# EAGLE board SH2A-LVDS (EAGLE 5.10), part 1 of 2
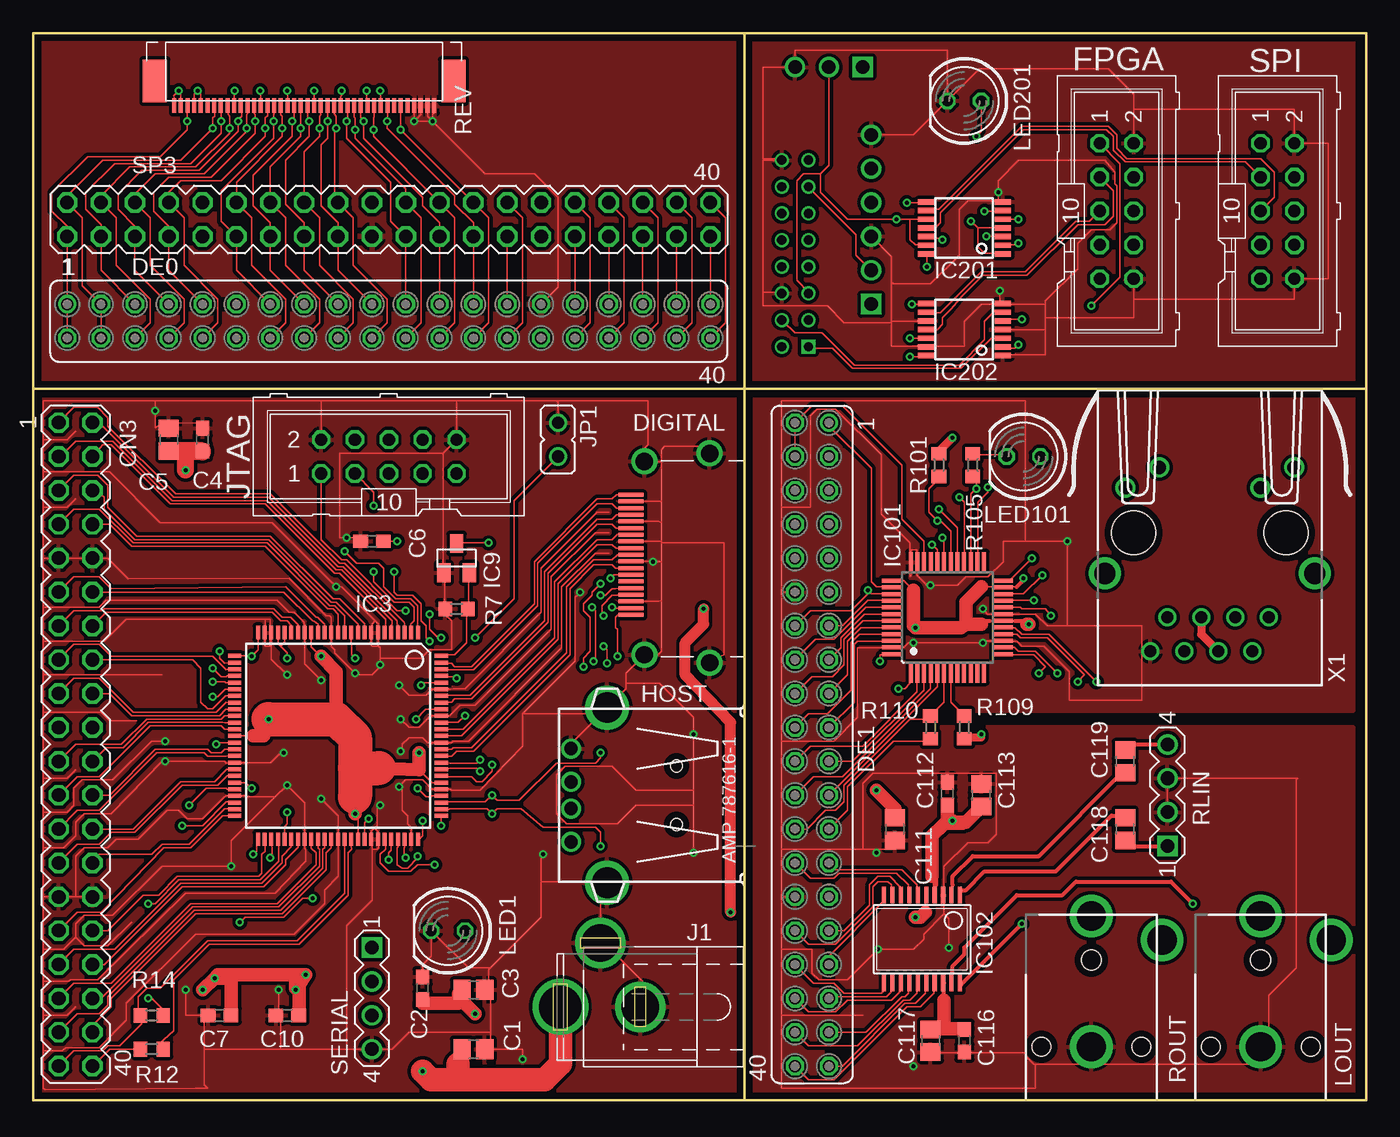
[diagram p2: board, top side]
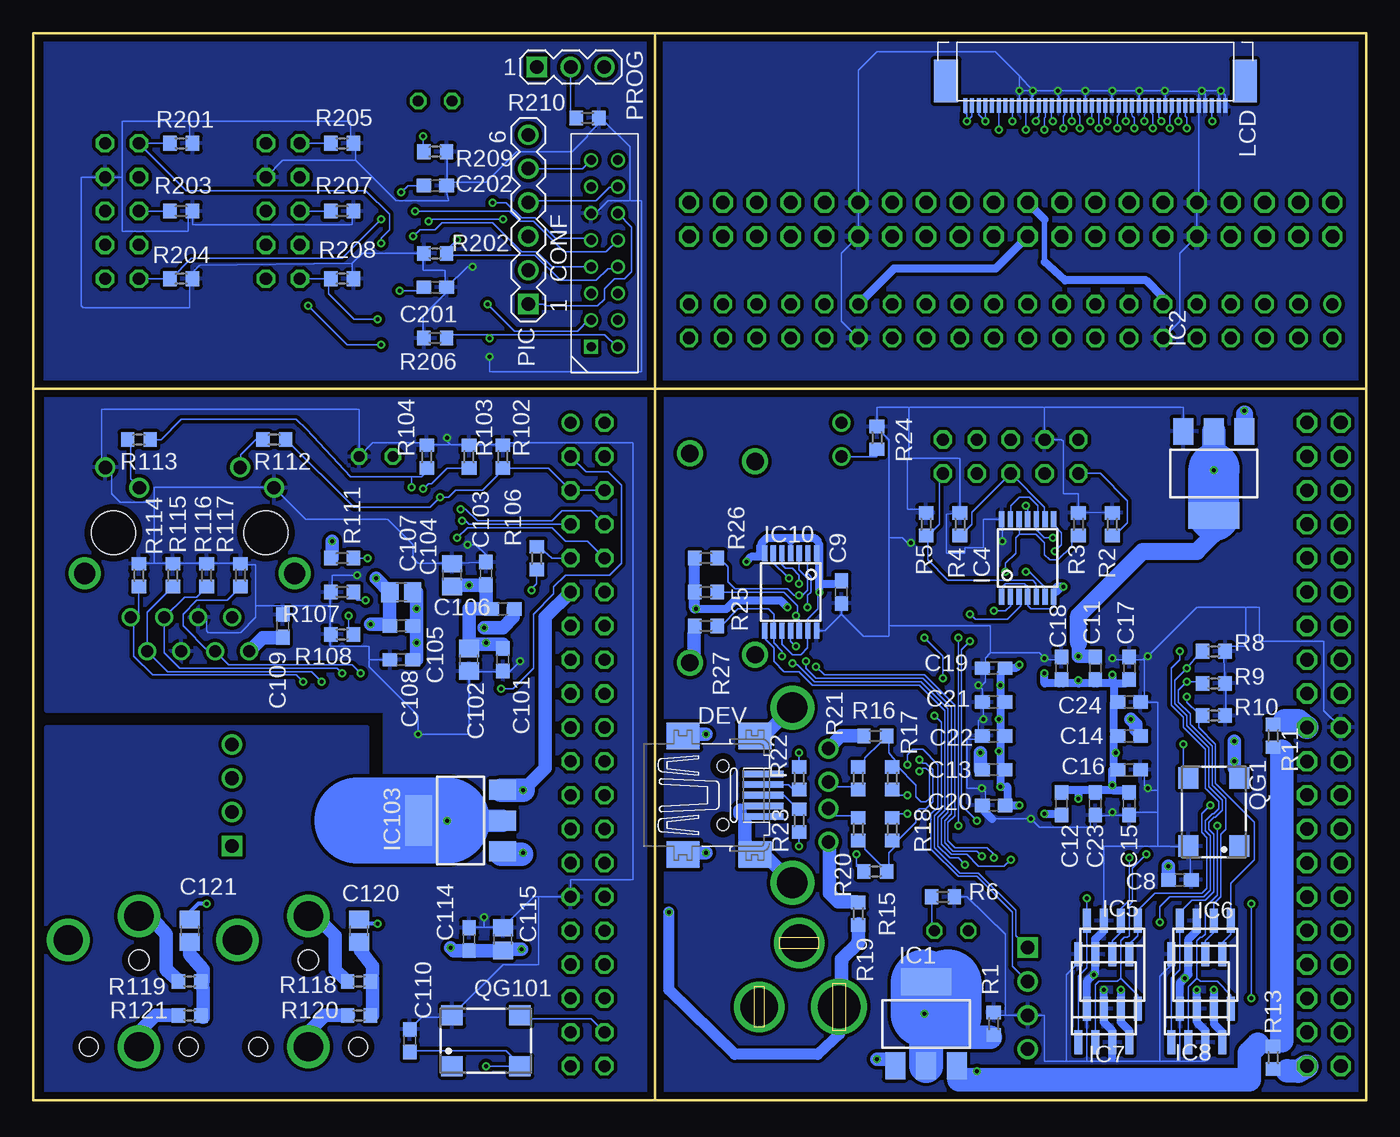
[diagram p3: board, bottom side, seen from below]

Size 100 x 80 mm. Coordinates in mm from the lower left corner, seen from the top.
Outline: 53.34,0 0,0 0,53.34
Outline: 53.34,0 100,0 100,53.34
Outline: 100,53.34 100,80 53.34,80
Outline: 53.34,80 0,80 0,53.34
Outline: 53.34,53.34 53.34,0
Outline: 0,53.34 53.34,53.34
Outline: 53.34,53.34 53.34,80
Outline: 53.34,53.34 100,53.34
Copper layers (1*16): Top 0.035mm / dielectric 1.53mm / Bottom 0.035mm
Design rules "pban_5mil-l2 *": minimum track width 5mil, minimum drill 0.3mm, track to track 5mil, track to pad 0.229mm, pad to pad 5mil, via to via 5mil, smd to smd 5mil, copper to edge 0.5mm, drill to drill 0.5mm, minimum pad ring 0.15mm, minimum via ring 0.15mm, stop-mask expansion 4mil, vias tented up to drill 0.35mm, thermal gap 10mil

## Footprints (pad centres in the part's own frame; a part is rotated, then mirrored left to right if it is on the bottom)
C2012 = smd 1.3 x 1.5: 1 -0.85,0; 2 0.85,0
C1608 = smd 1.1 x 1: 1 -0.85,0; 2 0.85,0
MA20-2 = drill 1.016 octagon: 1 -24.13,-1.27; 2 -24.13,1.27; 3 -21.59,-1.27; 4 -21.59,1.27; 5 -19.05,-1.27; 6 -19.05,1.27; 7 -16.51,-1.27; 8 -16.51,1.27; 9 -13.97,-1.27; 10 -13.97,1.27; 11 -11.43,-1.27; 12 -11.43,1.27; 13 -8.89,-1.27; 14 -8.89,1.27; 15 -6.35,-1.27; 16 -6.35,1.27; 17 -3.81,-1.27; 18 -3.81,1.27; 19 -1.27,-1.27; 20 -1.27,1.27; 21 1.27,-1.27; 22 1.27,1.27; 23 3.81,-1.27; 24 3.81,1.27; 25 6.35,-1.27; 26 6.35,1.27; 27 8.89,-1.27; 28 8.89,1.27; 29 11.43,-1.27; 30 11.43,1.27; 31 13.97,-1.27; 32 13.97,1.27; 33 16.51,-1.27; 34 16.51,1.27; 35 19.05,-1.27; 36 19.05,1.27; 37 21.59,-1.27; 38 21.59,1.27; 39 24.13,-1.27; 40 24.13,1.27
PHDSS-16 = drill 0.7 square: P$1 1,7 | drill 0.7 round: P$2 -1,7; P$3 1,5; P$4 -1,5; P$5 1,3; P$6 -1,3; P$7 1,1; P$8 -1,1; P$9 1,-1; P$10 -1,-1; P$11 1,-3; P$12 -1,-3; P$13 1,-5; P$14 -1,-5; P$15 1,-7; P$16 -1,-7
FE20-2 = drill 0.914 round: 1 -24.13,1.27 | drill 0.914 octagon: 2 -24.13,-1.27; 3 -21.59,1.27; 4 -21.59,-1.27; 5 -19.05,1.27; 6 -19.05,-1.27; 7 -16.51,1.27; 8 -16.51,-1.27; 9 -13.97,1.27; 10 -13.97,-1.27; 11 -11.43,1.27; 12 -11.43,-1.27; 13 -8.89,1.27; 14 -8.89,-1.27; 15 -6.35,1.27; 16 -6.35,-1.27; 17 -3.81,1.27; 18 -3.81,-1.27; 19 -1.27,1.27; 20 -1.27,-1.27; 21 1.27,1.27; 22 1.27,-1.27; 23 3.81,1.27; 24 3.81,-1.27; 25 6.35,1.27; 26 6.35,-1.27; 27 8.89,1.27; 28 8.89,-1.27; 29 11.43,1.27; 30 11.43,-1.27; 31 13.97,1.27; 32 13.97,-1.27; 33 16.51,1.27; 34 16.51,-1.27; 35 19.05,1.27; 36 19.05,-1.27; 37 21.59,1.27; 38 21.59,-1.27; 39 24.13,1.27; 40 24.13,-1.27
32005-201A = smd 3.1 x 0.5: 1 3,1.6; 2 3,0.8; 3 3,0; 4 3,-0.8; 5 3,-1.6 | smd 2.5 x 2: M1 -3,-4.45; M2 -3,4.45; M3 2.4,4.45; M4 2.4,-4.45 | hole 0.9: 0,2.2; 0,-2.2
HDMI-FCI-A-UPDATE = smd 0.3 x 1.9: 1 4.75,8.5; 2 4.25,8.5; 3 3.75,8.5; 4 3.25,8.5; 5 2.75,8.5; 6 2.25,8.5; 7 1.75,8.5; 8 1.25,8.5; 9 0.75,8.5; 10 0.25,8.5; 11 -0.25,8.5; 12 -0.75,8.5; 13 -1.25,8.5; 14 -1.75,8.5; 15 -2.25,8.5; 16 -2.75,8.5; 17 -3.25,8.5; 18 -3.75,8.5; 19 -4.25,8.5 | drill 1.3 round: 20 -7.85,2.6; 21 7.85,2.6; 22 -7.25,7.5; 23 7.25,7.5
ML10 = drill 0.914 octagon: 1 -5.08,-1.27; 2 -5.08,1.27; 3 -2.54,-1.27; 4 -2.54,1.27; 5 0,-1.27; 6 0,1.27; 7 2.54,-1.27; 8 2.54,1.27; 9 5.08,-1.27; 10 5.08,1.27
USB = drill 1 round: 1 -3.5,12.99; 2 -1,12.99; 3 1,12.99; 4 3.5,12.99 | drill 2.3 round: P$1 -6.57,10.28; P$2 6.57,10.28
SOT223 = smd 1.5 x 2: 1 -2.3,-3.15; 2 0,-3.15; 3 2.3,-3.15 | smd 3.8 x 2: 4 0,3.15
VQ100 = smd 1 x 0.3: 1 -7.75,6; 2 -7.75,5.5; 3 -7.75,5; 4 -7.75,4.5; 5 -7.75,4; 6 -7.75,3.5; 7 -7.75,3; 8 -7.75,2.5; 9 -7.75,2; 10 -7.75,1.5; 11 -7.75,1; 12 -7.75,0.5; 13 -7.75,0; 14 -7.75,-0.5; 15 -7.75,-1; 16 -7.75,-1.5; 17 -7.75,-2; 18 -7.75,-2.5; 19 -7.75,-3; 20 -7.75,-3.5; 21 -7.75,-4; 22 -7.75,-4.5; 23 -7.75,-5; 24 -7.75,-5.5; 25 -7.75,-6; 51 7.75,-6; 52 7.75,-5.5; 53 7.75,-5; 54 7.75,-4.5; 55 7.75,-4; 56 7.75,-3.5; 57 7.75,-3; 58 7.75,-2.5; 59 7.75,-2; 60 7.75,-1.5; 61 7.75,-1; 62 7.75,-0.5; 63 7.75,0; 64 7.75,0.5; 65 7.75,1; 66 7.75,1.5; 67 7.75,2; 68 7.75,2.5; 69 7.75,3; 70 7.75,3.5; 71 7.75,4; 72 7.75,4.5; 73 7.75,5; 74 7.75,5.5; 75 7.75,6 | smd 0.3 x 1: 26 -6,-7.75; 27 -5.5,-7.75; 28 -5,-7.75; 29 -4.5,-7.75; 30 -4,-7.75; 31 -3.5,-7.75; 32 -3,-7.75; 33 -2.5,-7.75; 34 -2,-7.75; 35 -1.5,-7.75; 36 -1,-7.75; 37 -0.5,-7.75; 38 0,-7.75; 39 0.5,-7.75; 40 1,-7.75; 41 1.5,-7.75; 42 2,-7.75; 43 2.5,-7.75; 44 3,-7.75; 45 3.5,-7.75; 46 4,-7.75; 47 4.5,-7.75; 48 5,-7.75; 49 5.5,-7.75; 50 6,-7.75; 76 6,7.75; 77 5.5,7.75; 78 5,7.75; 79 4.5,7.75; 80 4,7.75; 81 3.5,7.75; 82 3,7.75; 83 2.5,7.75; 84 2,7.75; 85 1.5,7.75; 86 1,7.75; 87 0.5,7.75; 88 0,7.75; 89 -0.5,7.75; 90 -1,7.75; 91 -1.5,7.75; 92 -2,7.75; 93 -2.5,7.75; 94 -3,7.75; 95 -3.5,7.75; 96 -4,7.75; 97 -4.5,7.75; 98 -5,7.75; 99 -5.5,7.75; 100 -6,7.75
PW_R-PDSO-G14 = smd 0.4 x 1.2: 1 -1.95,-2.9; 2 -1.3,-2.9; 3 -0.65,-2.9; 4 0,-2.9; 5 0.65,-2.9; 6 1.3,-2.9; 7 1.95,-2.9; 8 1.95,2.9; 9 1.3,2.9; 10 0.65,2.9; 11 0,2.9; 12 -0.65,2.9; 13 -1.3,2.9; 14 -1.95,2.9
AT45DB = smd 0.6 x 1.8: 1 -1.905,-3.3; 2 -0.635,-3.3; 3 0.635,-3.3; 4 1.905,-3.3; 5 1.905,3.3; 6 0.635,3.3; 7 -0.635,3.3; 8 -1.905,3.3
SOT23 = smd 1 x 1.4: 1 -0.95,-1.1; 2 0.95,-1.1; 3 0,1.1
LQFP48 = smd 1.5 x 0.3: 1 -4.15,2.75; 2 -4.15,2.25; 3 -4.15,1.75; 4 -4.15,1.25; 5 -4.15,0.75; 6 -4.15,0.25; 7 -4.15,-0.25; 8 -4.15,-0.75; 9 -4.15,-1.25; 10 -4.15,-1.75; 11 -4.15,-2.25; 12 -4.15,-2.75; 25 4.15,-2.75; 26 4.15,-2.25; 27 4.15,-1.75; 28 4.15,-1.25; 29 4.15,-0.75; 30 4.15,-0.25; 31 4.15,0.25; 32 4.15,0.75; 33 4.15,1.25; 34 4.15,1.75; 35 4.15,2.25; 36 4.15,2.75 | smd 0.3 x 1.5: 13 -2.75,-4.15; 14 -2.25,-4.15; 15 -1.75,-4.15; 16 -1.25,-4.15; 17 -0.75,-4.15; 18 -0.25,-4.15; 19 0.25,-4.15; 20 0.75,-4.15; 21 1.25,-4.15; 22 1.75,-4.15; 23 2.25,-4.15; 24 2.75,-4.15; 37 2.75,4.15; 38 2.25,4.15; 39 1.75,4.15; 40 1.25,4.15; 41 0.75,4.15; 42 0.25,4.15; 43 -0.25,4.15; 44 -0.75,4.15; 45 -1.25,4.15; 46 -1.75,4.15; 47 -2.25,4.15; 48 -2.75,4.15
SSOP20 = smd 0.305 x 1.245: 1 -2.857,-3.302; 2 -2.222,-3.302; 3 -1.587,-3.302; 4 -0.952,-3.302; 5 -0.317,-3.302; 6 0.318,-3.302; 7 0.953,-3.302; 8 1.588,-3.302; 9 2.223,-3.302; 10 2.858,-3.302; 11 2.858,3.302; 12 2.223,3.302; 13 1.588,3.302; 14 0.953,3.302; 15 0.318,3.302; 16 -0.317,3.302; 17 -0.952,3.302; 18 -1.587,3.302; 19 -2.222,3.302; 20 -2.857,3.302
SPC4077A = drill 2.8 round: 1 -3,0; 2 0,-4.8 | drill 3.2 round: 3 3,0
JP1A = drill 0.914 round: 1 0,-1.27; 2 0,1.27
FFC-40-0.5B-TYCO = smd 1.1 x 0.3: 1 -0.35,9.75; 2 -0.35,9.25; 3 -0.35,8.75; 4 -0.35,8.25; 5 -0.35,7.75; 6 -0.35,7.25; 7 -0.35,6.75; 8 -0.35,6.25; 9 -0.35,5.75; 10 -0.35,5.25; 11 -0.35,4.75; 12 -0.35,4.25; 13 -0.35,3.75; 14 -0.35,3.25; 15 -0.35,2.75; 16 -0.35,2.25; 17 -0.35,1.75; 18 -0.35,1.25; 19 -0.35,0.75; 20 -0.35,0.25; 21 -0.35,-0.25; 22 -0.35,-0.75; 23 -0.35,-1.25; 24 -0.35,-1.75; 25 -0.35,-2.25; 26 -0.35,-2.75; 27 -0.35,-3.25; 28 -0.35,-3.75; 29 -0.35,-4.25; 30 -0.35,-4.75; 31 -0.35,-5.25; 32 -0.35,-5.75; 33 -0.35,-6.25; 34 -0.35,-6.75; 35 -0.35,-7.25; 36 -0.35,-7.75; 37 -0.35,-8.25; 38 -0.35,-8.75; 39 -0.35,-9.25; 40 -0.35,-9.75 | smd 3.2 x 1.8: P$41 1.5,11.2; P$42 1.5,-11.2
LED5MM = drill 0.813 octagon: A -1.27,0; K 1.27,0
WBTOR1B = drill 2.2 round: S 0,-4; T 0,-13.792; T1 -5.309,-12 | hole 1.4: -3.75,-4; 3.75,-4 | hole 1.5: 0,-10.5
MA06-1A = drill 1.016 square: 1 -6.35,0 | drill 1.016 round: 2 -3.81,0; 3 -1.27,0; 4 1.27,0; 5 3.81,0; 6 6.35,0
MA03-1A = drill 1.016 square: 1 -2.54,0 | drill 1.016 round: 2 0,0; 3 2.54,0
SM77H = smd 1.6 x 1.5: 1 -2.55,-1.9; 2 2.55,-1.9; 3 2.55,1.9; 4 -2.55,1.9
R0603 = smd 1 x 1.1: 1 -0.85,0; 2 0.85,0
MA04-1A = drill 1.016 square: 1 -3.81,0 | drill 1.016 round: 2 -1.27,0; 3 1.27,0; 4 3.81,0
J0B = drill 0.9 pad 1.3 round: 1 -4.445,-1.27; 2 -3.175,1.27; 3 -1.905,-1.27; 4 -0.635,1.27; 5 0.635,-1.27; 6 1.905,1.27; 7 3.175,-1.27; 8 4.445,1.27 | drill 1 pad 1.422 round: 9 -6.325,-12.52; 10 -3.785,-11; 11 3.785,-12.52; 12 6.325,-11 | drill 1.6 pad 2.184 round: M1 -7.875,-4.57; M2 7.875,-4.57 | hole 3.3: 5.715,-7.62; -5.715,-7.62

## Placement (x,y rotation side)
C1  10u  [C2012]  33.02,3.81 0 top
C2  0.1u  [C1608]  29.21,8.38 90 top
C3  10u  [C2012]  33.02,8.26 0 top
C4  0.1u  [C1608]  12.7,49.53 90 top
C5  10u  [C2012]  10.16,49.53 90 top
C6  0.1u  [C1608]  25.4,41.91 180 top
C7  0.1u  [C1608]  13.97,6.35 180 top
C8  0.1u  [C1608]  13.97,16.51 180 bottom
C9  0.1u  [C1608]  39.37,38.1 90 bottom
C10  0.1u  [C1608]  19.05,6.35 180 top
C11  0.1u  [C1608]  20.32,32.38 270 bottom
C12  0.1u  [C1608]  22.86,22.23 90 bottom
C13  0.1u  [C1608]  27.94,24.77 0 bottom
C14  0.1u  [C1608]  17.78,27.3 180 bottom
C15  0.1u  [C1608]  17.78,22.23 90 bottom
C16  0.1u  [C1608]  17.78,24.77 180 bottom
C17  0.1u  [C1608]  17.78,32.38 270 bottom
C18  0.1u  [C1608]  22.86,32.38 270 bottom
C19  0.1u  [C1608]  27.94,32.38 0 bottom
C20  0.1u  [C1608]  27.94,22.1 0 bottom
C21  0.1u  [C1608]  27.94,29.84 0 bottom
C22  0.1u  [C1608]  27.94,27.3 0 bottom
C23  0.1u  [C1608]  20.32,22.23 90 bottom
C24  0.1u  [C1608]  17.78,29.84 180 bottom
C101  0.1u  [C1608]  64.77,33.02 90 bottom
C102  10u  [C2012]  67.31,33.02 90 bottom
C103  0.1u  [C1608]  66.04,39.5 270 bottom
C104  10u  [C2012]  68.58,39.37 270 bottom
C105  0.1u  [C1608]  72.39,35.56 0 bottom
C106  0.1u  [C1608]  64.77,36.83 180 bottom
C107  10u  [C2012]  72.39,38.1 0 bottom
C108  0.1u  [C1608]  72.39,33.02 0 bottom
C109  0.1u  [C1608]  81.28,35.56 270 bottom
C110  0.1u  [C1608]  71.75,4.45 270 bottom
C111  10u  [C2012]  64.64,20.32 270 top
C112  0.1u  [C1608]  68.58,22.99 90 top
C113  10u  [C2012]  71.12,22.86 90 top
C114  0.1u  [C1608]  67.31,12.06 270 bottom
C115  10u  [C2012]  64.77,12.06 270 bottom
C116  0.1u  [C1608]  69.85,4.45 270 top
C117  10u  [C2012]  67.31,4.45 270 top
C118  10u  [C2012]  81.92,20.32 270 top
C119  10u  [C2012]  81.92,25.4 90 top
C120  10u  [C2012]  75.56,12.7 270 bottom
C121  10u  [C2012]  88.27,12.7 270 bottom
C201  0.1u  [C1608]  69.85,60.96 180 bottom
C202  0.1u  [C1608]  69.85,68.58 180 bottom
CN3  [MA20-2]  3.17,26.67 270 top
CONF  PHDSS-16B  [PHDSS-16]  57.15,63.5 180 bottom
DE0  [FE20-2]  26.67,58.42 0 top
DE1  [FE20-2]  58.42,26.67 270 top
DEV  MINI-USB-SHELD-32005-201A  [32005-201A]  48.26,22.86 0 bottom
DIGITAL  [HDMI-FCI-A-UPDATE]  53.34,40.64 90 top
FPGA  [ML10]  81.28,66.67 270 top
HOST  [USB]  53.34,22.86 90 top
IC1  LD117AS33TR-A  [SOT223]  33.02,5.71 0 bottom
IC2  LD117AS12TR-A  [SOT223]  11.43,46.99 180 bottom
IC3  XC3S200AVQ100  [VQ100]  22.86,27.3 270 top
IC4  74VHC125TSSOP  [PW_R-PDSO-G14]  25.4,40.64 0 bottom
IC5  AT45DB081  [AT45DB]  19.05,10.16 180 bottom
IC6  AT45DB081  [AT45DB]  12.06,10.16 180 bottom
IC7  M25P  [AT45DB]  19.68,7.62 0 bottom
IC8  M25P  [AT45DB]  12.7,7.62 0 bottom
IC9  TCM809R(3.3V)  [SOT23]  31.75,40.64 0 top
IC10  74CBT3125TSSOP  [PW_R-PDSO-G14]  43.18,38.1 180 bottom
IC101  DP83848C  [LQFP48]  68.58,36.2 90 top
IC102  AK4556  [SSOP20]  66.67,12.06 180 top
IC103  LD117AS33TR-A  [SOT223]  67.94,20.95 90 bottom
IC201  74VHC125TSSOP  [PW_R-PDSO-G14]  69.85,65.41 90 top
IC202  74VHC125TSSOP  [PW_R-PDSO-G14]  69.85,57.78 90 top
J1  [SPC4077A]  42.55,6.99 180 top
JP1  [JP1A]  39.37,49.53 180 top
JTAG  [ML10]  26.67,48.26 0 top
LCD  FFC-40TYCO-0.5B  [FFC-40-0.5B-TYCO]  20.32,74.93 90 bottom
LED1  [LED5MM]  31.11,12.7 180 top
LED101  [LED5MM]  74.3,48.26 180 top
LED201  [LED5MM]  69.85,74.93 180 top
LOUT  WBTOR1B  [WBTOR1B]  92.08,0 180 top
PIC  [MA06-1A]  62.87,66.04 90 bottom
PROG  [MA03-1A]  59.69,77.47 0 bottom
QG1  27MHz  [SM77H]  11.43,21.59 90 bottom
QG101  24.576MHz  [SM77H]  66.04,4.45 0 bottom
R1  0  [R0603]  27.94,5.71 90 bottom
R2  4.7k  [R0603]  19.05,43.18 90 bottom
R3  4.7k  [R0603]  21.59,43.18 90 bottom
R4  4.7k  [R0603]  30.48,43.18 90 bottom
R5  4.7k  [R0603]  33.02,43.18 90 bottom
R6  220  [R0603]  31.75,15.24 0 bottom
R7  4.7k  [R0603]  31.75,36.83 180 top
R8  4.7k  [R0603]  11.43,33.66 0 bottom
R9  4.7k  [R0603]  11.43,31.24 0 bottom
R10  4.7k  [R0603]  11.43,28.83 0 bottom
R11  0  [R0603]  6.99,27.3 270 bottom
R12  0  [R0603]  8.89,3.81 0 top
R13  0  [R0603]  6.99,3.17 90 bottom
R14  220  [R0603]  8.89,6.35 0 top
R15  15k  [R0603]  36.83,17.14 0 bottom
R16  15k  [R0603]  36.83,27.3 0 bottom
R17  1.5k  [R0603]  35.56,24.13 270 bottom
R18  1.5k  [R0603]  35.56,20.32 90 bottom
R19  0  [R0603]  38.1,13.97 90 bottom
R20  22  [R0603]  38.1,20.32 90 bottom
R21  22  [R0603]  38.1,24.13 270 bottom
R22  22  [R0603]  42.55,24.13 270 bottom
R23  22  [R0603]  42.55,20.95 90 bottom
R24  4.7k  [R0603]  36.7,49.66 270 bottom
R25  10k  [R0603]  49.53,38.1 180 bottom
R26  10k  [R0603]  49.53,40.64 180 bottom
R27  10k  [R0603]  49.53,35.56 0 bottom
R101  1.5k  [R0603]  67.94,47.62 270 top
R102  2.2k  [R0603]  64.77,48.26 90 bottom
R103  2.2k  [R0603]  67.31,48.26 90 bottom
R104  2.2k  [R0603]  70.48,48.26 90 bottom
R105  220  [R0603]  70.48,47.62 90 top
R106  1k  [R0603]  62.23,40.64 270 bottom
R107  2.2k  [R0603]  76.83,38.1 180 bottom
R108  2.2k  [R0603]  76.83,34.92 180 bottom
R109  10k  [R0603]  69.85,27.94 270 top
R110  1k  [R0603]  67.31,27.94 90 top
R111  4.87k  [R0603]  76.83,40.64 180 bottom
R112  120  [R0603]  81.92,49.53 180 bottom
R113  120  [R0603]  92.08,49.53 180 bottom
R114  50  [R0603]  92.08,39.37 270 bottom
R115  50  [R0603]  89.53,39.37 270 bottom
R116  50  [R0603]  87,39.37 270 bottom
R117  50  [R0603]  84.45,39.37 270 bottom
R118  220  [R0603]  75.56,8.89 180 bottom
R119  220  [R0603]  88.27,8.89 180 bottom
R120  10k  [R0603]  75.56,6.35 0 bottom
R121  10k  [R0603]  88.27,6.35 0 bottom
R201  4.7k  [R0603]  88.9,71.75 0 bottom
R202  4.7k  [R0603]  69.85,63.5 180 bottom
R203  4.7k  [R0603]  88.9,66.67 0 bottom
R204  4.7k  [R0603]  88.9,61.59 0 bottom
R205  4.7k  [R0603]  76.83,71.75 0 bottom
R206  4.7k  [R0603]  69.85,57.15 180 bottom
R207  4.7k  [R0603]  76.83,66.67 0 bottom
R208  4.7k  [R0603]  76.83,61.59 0 bottom
R209  220  [R0603]  69.85,71.12 0 bottom
R210  4.7k  [R0603]  58.42,73.66 0 bottom
REV  FFC-40TYCO-0.5B  [FFC-40-0.5B-TYCO]  20.32,74.93 90 top
RLIN  [MA04-1A]  85.09,22.86 90 top
ROUT  WBTOR1B  [WBTOR1B]  79.38,0 180 top
SERIAL  [MA04-1A]  25.4,7.62 270 top
SP3  [MA20-2]  26.67,66.04 0 top
SPI  [ML10]  93.34,66.67 270 top
X1  J0011D21BNL  [J0B]  88.27,34.92 180 top

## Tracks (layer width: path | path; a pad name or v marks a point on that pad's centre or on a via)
C_DI  (via drill 0.3)
  Top 0.127: v73.91,66.04 72.64,66.04 IC201.5
  Bottom 0.127: SPI.9 R204.1 89.66,61.59 88.14,63.12 76.83,63.12 v73.91,66.04
C_DO
  Top 0.127: SPI.3 90.93,70.36 81.92,70.36 81.03,71.25 81.03,72.26 80.52,72.77 74.3,72.77 68.07,66.55 68.07,65.79 67.69,65.41 IC201.11
C_SCK  (via drill 0.3)
  Top 0.127: v73.91,64.26 73.66,64.14 72.64,64.14 IC201.2
  Bottom 0.127: R201.1 SPI.1 88.52,68.2 75.06,68.2 73.28,66.42 73.28,65.28 73.91,64.64 v73.91,64.26
C_SS
  Top 0.127: SPI.5 93.09,67.69 93.09,69.6 92.08,70.61 82.04,70.61 81.28,71.37 81.28,72.39 80.64,73.03 74.17,73.03 67.94,66.8 67.06,66.8 IC201.9
  Bottom 0.127: SPI.5 R203.1
C_TCK  (via drill 0.3)
  Top 0.127: v73.91,56.64 73.66,56.39 72.77,56.39 IC202.2 | v79.38,59.56 81.53,61.72 81.53,70.23 FPGA.1
  Bottom 0.127: FPGA.1 R205.1 | v73.91,56.64 76.45,56.64 v79.38,59.56
C_TDI  (via drill 0.3)
  Top 0.127: v74.17,58.55 72.77,58.55 IC202.5
  Bottom 0.127: 77.85,61.59 FPGA.9 | 77.85,61.59 R208.1 77.72,61.59 | v74.17,58.55 75.95,58.55 77.85,60.45 77.85,61.59
C_TDO
  Top 0.127: FPGA.3 81.03,68.2 81.03,66.29 80.39,65.66 78.36,65.66 74.55,61.85 71.25,61.85 69.72,60.33 68.83,59.31 68.2,58.67 68.2,58.17 67.82,57.78 IC202.11
C_TMS
  Top 0.127: FPGA.5 79.25,65.91 78.23,65.91 74.42,62.1 71.12,62.1 68.07,59.05 67.06,59.05 IC202.9
  Bottom 0.127: FPGA.5 R207.1
CCLK  (via drill 0.3)
  Top 0.127: v17.78,18.16 17.91,18.29 17.91,18.8 IC3.53
  Bottom 0.127: IC7.6 19.05,11.94 18.41,12.57 IC5.2 18.41,14.35 17.78,14.99 v17.78,18.16
CEC1  (via drill 0.3)
  Top 0.127: DIGITAL.13 43.58,39.39 v43.31,39.12
  Bottom 0.127: v43.31,39.12 44.58,40.39 44.58,40.9 IC10.6
CH0N
  Top 0.127: DIGITAL.9 43.7,41.39 43.43,41.66 42.29,41.66 39.37,38.73 39.37,34.54 32.13,27.3 IC3.88
CH0P
  Top 0.127: DIGITAL.7 43.97,42.39 43.81,42.42 43.43,42.04 42.29,42.04 39.12,38.86 39.12,34.67 32.26,27.81 30.62,27.81 IC3.89
CH1N
  Top 0.127: DIGITAL.6 43.72,42.89 43.43,43.18 42.29,43.18 38.61,39.5 38.61,35.81 32.89,30.1 31.62,30.1 31.37,29.84 30.65,29.84 IC3.93
CH1P
  Top 0.127: DIGITAL.4 43.74,43.89 43.43,43.56 42.29,43.56 38.35,39.62 38.35,35.94 32.77,30.35 30.69,30.35 IC3.94
CH2N
  Top 0.127: DIGITAL.3 43.76,44.39 43.43,44.7 42.29,44.7 37.85,40.26 37.85,37.08 33.02,32.26 30.66,32.26 IC3.98
CH2P
  Top 0.127: DIGITAL.1 43.76,45.39 43.43,45.09 42.29,45.09 37.59,40.39 37.59,37.21 32.89,32.51 31.62,32.51 31.37,32.77 30.65,32.77 IC3.99
CH3N
  Top 0.127: DIGITAL.12 43.68,39.89 43.43,40.13 42.04,40.13 40.26,38.35 40.26,33.4 33.02,26.16 31.75,26.16 31.37,25.78 30.63,25.78 IC3.85
CH3P
  Top 0.127: DIGITAL.10 43.82,40.89 43.43,40.51 42.04,40.51 40.01,38.48 40.01,33.53 32.89,26.42 31.5,26.42 31.37,26.29 30.63,26.29 IC3.86
CH4  (via drill 0.3)
  Top 0.127: v42.55,38.73 41.91,38.1 41.91,37.85 41.27,37.21 41.27,36.7 41.78,36.2 41.78,33.66 41.27,33.15 v41.27,32.51 | v27.94,18.16 27.81,18.29 27.81,18.92 27.86,18.97 IC3.73
  Bottom 0.127: IC10.5 43.83,40.15 43.56,39.88 43.05,39.88 42.55,39.37 v42.55,38.73 | v41.27,32.51 40.64,31.88 33.15,31.88 30.86,29.59 30.86,21.34 31.37,20.83 31.37,19.43 30.86,18.92 28.45,18.92 27.94,18.41 v27.94,18.16
CH5  (via drill 0.3)
  Top 0.127: 27.3,19.43 IC3.72 27.36,18.98 27.3,18.92 27.3,17.65 27.69,17.4 28.07,17.4 28.83,18.16 v28.83,18.29 | v42.04,32.89 42.16,33.02 42.16,36.7 v41.91,36.96
  Bottom 0.127: v41.91,36.96 41.91,37.85 41.66,38.1 41.66,39.24 41.91,39.5 41.91,41.02 IC10.2 | v42.04,32.89 42.04,32.38 41.27,31.62 33.27,31.62 31.11,29.46 31.11,21.46 31.62,20.95 31.62,19.3 30.99,18.67 29.21,18.67 v28.83,18.29
CH6  (via drill 0.3)
  Top 0.127: v43.05,32.77 43.05,33.78 v42.8,34.04 | v26.67,18.03 26.67,18.54 26.86,18.73 IC3.71
  Bottom 0.127: 43.18,35.31 IC10.11 43.18,34.42 v42.8,34.04 | v43.05,32.77 42.93,32.64 42.67,32.64 41.4,31.37 33.4,31.37 31.37,29.34 31.37,21.59 31.88,21.08 31.88,19.18 31.11,18.41 29.97,18.41 29.08,17.53 27.18,17.53 v26.67,18.03
CH7  (via drill 0.3)
  Top 0.127: v30.1,17.65 28.83,17.65 28.32,17.14 26.67,17.14 26.04,17.78 26.04,18.41 26.42,18.8 26.42,19.43 IC3.70
  Bottom 0.127: v30.1,17.65 30.61,18.16 31.24,18.16 32.13,19.05 32.13,21.21 31.62,21.72 31.62,29.21 33.53,31.11 41.53,31.11 42.55,32.13 43.69,32.13 44.45,32.89 44.45,33.91 45.09,34.54 45.09,35.18 IC10.8
CH8N  (via drill 0.3)
  Top 0.127: IC3.84 30.96,25.3 31.24,25.27 33.27,25.27 v33.53,25.53
  Bottom 0.127: v33.53,25.53 33.27,25.27 33.02,25.27 32.51,24.77 32.51,22.35 33.02,21.84 33.53,21.84 33.78,21.59 33.78,20.83 35.18,19.43 35.56,19.56 35.52,19.43 R18.1 | R18.1 35.56,19.3 | 35.81,17.14 36.2,17.14 36.32,17.65 36.45,17.65 37.59,18.8 37.59,19.05 37.68,19.43 R20.1 | R15.2 35.94,17.14 35.81,17.02 35.81,17.14 | 35.81,17.14 35.81,18.54 35.31,19.05 35.31,19.22 R18.1
CH8P  (via drill 0.3)
  Top 0.127: IC3.83 31.07,24.8 31.24,24.89 33.27,24.89 v33.53,24.64
  Bottom 0.127: v33.53,24.64 33.27,24.89 33.02,24.89 32.77,24.64 32.77,22.61 33.02,22.35 33.4,22.35 33.78,22.73 33.78,23.62 35.18,25.02 | 35.18,25.02 35.56,24.89 35.56,24.64 35.6,24.77 R17.1 | R17.1 35.56,25.15 | 35.81,27.3 36.2,27.3 36.2,26.8 36.45,26.8 37.59,25.65 37.72,25.15 37.93,25.15 R21.1 | R16.2 35.98,27.47 35.81,27.43 35.81,27.3 | 35.18,25.02 35.18,25.27 35.81,26.04 35.81,27.3 | 35.18,25.02 R17.1
CH9N  (via drill 0.3)
  Top 0.127: v42.55,26.04 42.55,25.65 42.16,25.27 39.24,25.27 36.45,22.48 34.8,22.48 v34.42,22.86 33.91,22.35 31.11,22.35 31.07,22.3 IC3.78
  Bottom 0.127: v42.55,26.04 R22.1 | v34.42,22.86 35.31,22.86 35.52,22.99 R17.2
CH9P  (via drill 0.3)
  Top 0.127: IC3.77 31.2,21.8 31.24,21.84 34.04,21.84 v34.42,21.46 34.8,21.84 36.58,21.84 38.23,20.45 42.16,20.45 42.55,20.07 v42.55,19.05
  Bottom 0.127: v34.42,21.46 35.47,21.46 R18.2 | v42.55,19.05 R23.1
CN3_0
  Top 0.127: CN3.1 3.05,51.94 4.83,51.94 5.59,51.18 5.59,50.55 10.67,45.47 17.78,45.47 22.99,40.26 23.37,40.26 27.81,35.81 27.86,35.73 IC3.3
CN3_1
  Top 0.127: CN3.2 4.7,50.55 5.21,50.55 10.54,45.21 17.65,45.21 22.86,40.01 23.24,40.01 27.3,35.94 27.3,35.69 27.36,35.62 IC3.4
CN3_2
  Top 0.127: CN3.3 2.03,48.26 3.17,49.4 5.97,49.4 10.41,44.96 17.53,44.96 22.73,39.75 23.11,39.75 26.92,35.94 26.92,35.69 26.86,35.62 IC3.5
CN3_3
  Top 0.127: CN3.4 5.21,49.15 5.84,49.15 10.29,44.7 17.4,44.7 22.61,39.5 22.99,39.5 26.42,36.07 26.42,35.56 26.36,35.5 IC3.6
CN3_3V3  (via drill 0.3)
  Top 0.127: IC3.92 29.43,29.3 v28.7,28.57 | IC3.96 29.27,31.3 v29.08,31.11 | IC3.55 18.86,20.51 19.05,20.7 v19.05,21.59 | IC3.67 24.86,20.8 v25.15,21.08 | IC3.79 29.92,22.8 29.84,22.73 29.46,22.73 v28.83,23.37 | IC3.11 23.86,34.31 23.88,34.29 23.88,33.4 v24.13,33.15 | IC3.26 16.35,33.3 v16.38,33.27 16.86,33.75 IC3.25 | IC3.22 18.36,34.22 18.54,34.04 | 18.54,34.04 19.05,33.53 v19.05,33.15 | IC3.21 18.86,34.35 18.54,34.04 | IC3.45 15.95,23.8 v16.38,23.37 | 19.94,6.35 C10.1 | 14.86,6.39 C7.1 | v27.3,41.91 C6.1 | IC9.3 31.71,41.99 32,41.78 v34.16,41.78
  Top 1.016: 19.94,6.35 19.94,8.64 v20.45,9.4 19.68,9.4 | v13.59,9.14 14.86,9.14 14.86,6.39 | v12.7,8.26 v13.59,9.14 | v13.59,9.14 13.84,9.4 19.68,9.4 | 19.68,9.4 19.68,8.38
  Bottom 0.127: IC10.14 40.62,35.2 39.37,36.45 | 39.37,36.45 C9.1 | 28.57,32.17 28.57,31.37 28.83,31.11 v29.08,31.11 28.79,30.82 C21.1 28.7,29.76 v28.7,28.57 28.96,28.57 29.08,28.45 29.08,27.6 C22.1 28.83,27.3 29.08,27.05 29.97,27.05 29.97,23.37 v28.83,23.37 28.57,23.11 28.57,21.88 C20.1 | 28.57,32.17 C19.1 | v19.05,21.59 19.3,21.34 19.56,21.34 | 19.56,21.34 20.28,21.34 C23.1 20.32,21.21 20.7,20.83 20.7,20.45 24.51,20.45 v25.15,21.08 28.07,21.08 | C18.1 23.07,33.02 23.88,33.02 24,33.15 v24.13,33.15 24.51,33.53 28.19,33.53 | v16.38,33.27 16.51,33.27 16.76,33.02 17.57,33.02 C17.1 18,33.02 18.8,33.02 18.92,33.15 v19.05,33.15 | C16.1 16.64,24.47 16.64,23.62 v16.38,23.37 16.26,23.24 15.62,23.24 | 16.64,29.84 C24.1 | 15.62,23.24 15.62,29.84 16.64,29.84 | 16.64,29.84 16.64,33.02 v16.38,33.27 | 28.57,32.17 28.57,33.15 28.19,33.53 | 19.56,21.34 19.52,21.38 C15.1 17.74,21.63 17.78,21.59 15.62,21.59 | IC2.3 13.73,51.93 13.72,51.94 24.13,51.94 | 24.13,51.94 JTAG.4 22.86,49.53 22.73,49.4 22.73,45.47 21.59,45.47 21.59,44.07 | 34.29,51.94 36.7,51.94 R24.1 36.7,50.42 35.81,49.53 35.81,42.16 | 34.29,51.94 24.13,51.94 | 10.67,28.32 10.67,28.7 10.41,28.7 10.54,28.96 R10.2 10.54,29 10.54,31.24 R9.2 10.67,33.06 10.67,33.53 10.79,33.66 | CN3.19 3.17,29.21 3.17,34.42 8,34.42 8,36.96 9.02,36.96 | 10.79,33.95 10.88,33.95 10.79,34.04 | 10.79,33.95 R8.2 10.79,33.66 | 12.7,19.05 12.69,18.91 15.62,19.05 | 13.21,19.05 13.21,16.51 C8.1 | 12.7,19.05 QG1.4 12.7,18.29 | 15.62,19.05 13.21,19.05 | 13.21,19.05 12.7,19.05 | 15.62,19.05 19.68,19.05 IC5.3 19.68,12.7 | 15.62,19.05 15.62,21.59 | 15.62,21.59 15.62,23.24
  Bottom 0.127: 10.79,34.04 10.79,33.95 | 10.79,33.95 10.79,33.66 | 9.02,36.96 12.7,36.96 v16.38,33.27 | 9.02,36.96 9.02,34.04 10.79,34.04 | R1.2 27.94,6.35 27.05,6.35 | 27.05,6.35 SERIAL.3 24.13,6.35 24.13,2.92 22.48,2.92 | 20.95,3.81 IC5.5 | 20.95,3.81 20.95,2.92 19.05,2.92 | 12.7,12.7 IC6.3 | IC8.3 12.06,5.21 | IC7.3 19.05,5.21 | 13.97,2.92 IC6.5 | 12.06,3.17 12.06,2.92 13.97,2.92 | 13.97,2.92 15.49,2.92 | 19.05,2.92 19.05,3.17 | 22.48,2.92 20.96,2.92 20.95,3.81 | IC8.8 14.61,10.16 15.49,9.27 15.49,2.92 | 15.49,2.92 19.05,2.92 | IC7.8 21.59,10.29 22.48,9.4 22.48,2.92 | 27.3,43.56 v27.3,41.91 | 27.3,43.56 IC4.14 | 34.29,48.13 30.48,48.13 R4.2 31.5,43.94 31.5,41.02 30.1,41.02 30.1,41.4 28.7,41.4 28.7,43.56 27.3,43.56 | 34.29,48.13 34.42,48.13 34.42,44.32 33.02,44.32 R5.2 | 21.72,44.07 21.46,43.94 | 21.59,44.07 21.72,44.07 | 21.59,44.07 21.46,44.07 R2.2 | 21.59,44.07 21.46,43.94 | 21.46,43.94 21.34,43.94 | 34.29,51.94 34.29,48.13 | 39.37,36.45 37.72,34.8 35.81,34.8 35.81,35.56 | 35.81,35.56 28.19,35.56 28.19,33.53 | 27.05,6.35 27.05,12.45 29.97,15.24 R6.2 | 35.81,35.56 35.81,42.16 | R3.2 21.72,43.98 21.72,44.07 | v34.16,41.78 34.42,41.78 34.8,42.16 35.81,42.16
  Bottom 0.61: 28.07,21.08 28.57,21.59 28.57,21.88 | IC5.5 20.95,8.89 v20.45,9.4 20.32,9.53 IC7.7 20.32,12.06 19.68,12.7 | IC6.5 13.97,8.76 v13.59,9.14 13.34,9.4 IC8.7 13.34,12.06 12.7,12.7 | 12.06,5.21 12.7,5.84 IC6.6 v12.7,8.26 | 19.05,5.21 19.68,5.84 IC5.6 v19.68,8.26 | IC8.3 12.06,3.17 | 19.05,3.17 IC7.3
  pour Bottom (isolate 0.254): 0.64,0.64 52.7,0.64 52.7,52.7 0.64,52.7
CN3_4
  Top 0.127: CN3.5 3.05,46.86 4.83,46.86 5.59,46.1 5.59,44.45 7.75,42.29 17.78,42.29 22.48,37.59 22.99,37.59 24.86,35.72 IC3.9
CN3_5
  Top 0.127: CN3.6 4.7,45.72 5.33,45.21 5.33,44.32 7.62,42.04 17.65,42.04 22.35,37.34 22.73,37.34 24.38,35.69 24.38,35.05 IC3.10
CN3_5V  (via drill 0.3)
  Top 0.127: DIGITAL.18 43.5,36.89 v43.43,36.96 | C1.1 32.13,3.01 31.88,2.67 32,1.52
  Top 0.813: v52.32,14.1 52.32,28.32 48.9,31.88 48.9,34.29 50.29,35.69 v50.29,36.83
  Top 1.778: v29.21,2.16 29.84,1.52 31.88,1.52 31.88,2.67 | J1.3 39.55,2.71 38.35,1.52 32,1.52
  Bottom 0.127: v50.29,36.83 50.38,36.92 50.47,36.83 | 6.35,26.16 R11.2 | 6.35,4.45 R13.2 7.53,4.03 8.13,4.19 | 30.57,1.52 IC1.3 30.5,1.8 v29.21,2.16 | 38.1,13.21 38.39,13.04 R19.1 38.39,12.91 39.5,7.24 | J1.3 39.37,7.16
  Bottom 0.61: v43.43,36.96 43.94,37.47 47.37,37.47 48.01,36.83 v50.29,36.83
  Bottom 0.813: R26.2 R25.2 50.38,36.92 | 39.5,7.24 39.5,4.95 41.15,3.43 47.37,3.43 52.32,8.26 v52.32,14.1
  Bottom 1.016: 38.1,13.21 38.1,11.81 39.37,10.54 39.37,7.16
  Bottom 1.778: 6.35,4.45 6.35,26.16 | 8.13,4.19 8.76,3.56 8.76,1.52 30.57,1.52
CN3_6
  Top 0.127: IC3.12 23.36,34.93 | CN3.7 3.05,44.32 4.95,44.32 7.49,41.78 17.53,41.78 22.23,37.08 22.61,37.08 23.37,36.32 IC3.12 | IC3.12 23.37,35.06 | IC3.12 23.37,34.92 | IC3.12
CN3_7
  Top 0.127: CN3.8 5.71,43.18 7.37,41.53 17.4,41.53 22.1,36.83 22.48,36.83 22.86,36.45 IC3.13
CN3_8
  Top 0.127: CN3.11 3.05,39.24 4.95,39.24 5.84,38.35 18.92,38.48 21.21,36.2 21.34,36.2 21.86,35.67 IC3.15
CN3_9
  Top 0.127: CN3.12 18.8,38.1 20.95,35.94 21.08,35.92 21.36,35.66 IC3.16
CN3_10
  Top 0.127: CN3.13 3.05,36.7 5.21,36.7 5.33,36.83 18.03,36.83 18.67,36.2 19.3,36.2 19.86,35.64 IC3.19
CN3_11
  Top 0.127: CN3.14 5.46,36.58 17.91,36.58 18.54,35.94 19.05,35.94 19.36,35.62 IC3.20
CN3_12
  Top 0.127: CN3.15 3.05,34.16 4.95,34.16 5.84,33.27 13.46,33.27 14.48,32.26 14.53,32.3 IC3.28
CN3_13
  Top 0.127: CN3.16 11.94,33.02 12.57,32.38 12.57,29.84 13.08,29.34 13.46,29.34 14.43,30.3 IC3.32
CN3_14
  Top 0.127: CN3.17 3.05,31.62 4.95,31.62 7.49,29.08 13.72,29.08 14.48,29.84 14.64,29.8 IC3.33
CN3_15
  Top 0.127: IC3.34 14.45,29.3 13.97,28.83 7.37,28.83 5.71,30.48 CN3.18
CN3_16
  Top 0.127: CN3.21 3.17,26.67 6.6,26.67 8.51,28.57 14.1,28.57 14.35,28.83 14.45,28.8 IC3.35
CN3_17
  Top 0.127: CN3.22 5.46,26.42 6.73,26.42 8.64,28.32 14.22,28.32 14.37,28.3 IC3.36
CN3_18
  Top 0.127: CN3.23 3.3,24.26 4.95,24.26 8.76,28.07 14.1,28.07 14.36,27.8 IC3.37
CN3_19
  Top 0.127: CN3.24 5.71,22.86 9.14,26.29 13.08,26.29 13.34,26.04 14.1,26.04 14.37,26.3 IC3.40
CN3_20
  Top 0.127: CN3.25 3.3,21.72 4.95,21.72 9.27,26.04 12.83,26.04 13.08,25.78 14.48,25.78 14.88,25.8 IC3.41
CN3_21
  Top 0.127: CN3.26 7.49,20.32 11.05,23.88 13.59,23.88 14.52,24.8 IC3.43
CN3_22
  Top 0.127: CN3.27 3.3,19.18 4.95,19.18 5.84,20.07 7.62,20.07 11.18,23.62 13.84,23.62 14.53,24.3 IC3.44
CN3_23
  Top 0.127: CN3.28 4.45,17.91 4.95,18.41 8.89,18.41 9.65,19.18 11.68,19.18 14.35,21.84 14.61,21.84 14.69,21.8 IC3.49
CN3_24
  Top 0.127: CN3.31 3.3,14.1 5.08,14.1 9.78,18.92 11.81,18.92 14.22,21.34 14.48,21.34 14.51,21.3 IC3.50
CN3_25
  Top 0.127: CN3.32 5.59,12.7 8.26,15.37 9.4,15.37 10.79,16.76 16.89,16.76 17.14,17.02 17.14,18.41 17.4,18.67 17.4,19.05 17.36,19.22 IC3.52
CN3_26
  Top 0.127: CN3.33 3.05,11.3 6.1,11.3 11.05,16.26 17.14,16.26 18.67,17.78 18.67,18.29 19.36,18.98 IC3.56
CN3_27
  Top 0.127: CN3.34 5.33,10.16 11.18,16 17.27,16 18.92,17.65 18.92,18.03 19.86,18.97 IC3.57
CN3_28
  Top 0.127: CN3.35 3.05,8.76 5.84,8.76 11.81,14.73 18.29,14.73 21.21,17.65 21.21,18.54 20.86,18.89 IC3.59
CN3_29
  Top 0.127: CN3.36 5.08,7.62 11.94,14.48 18.41,14.48 21.46,17.53 21.46,18.8 21.36,18.9 IC3.60
CN3_30
  Top 0.127: CN3.37 3.3,6.48 4.95,6.48 5.59,7.11 5.59,7.75 12.06,14.22 18.54,14.22 21.72,17.4 21.72,18.8 21.86,18.91 IC3.61
CN3_31
  Top 0.127: CN3.38 4.45,5.59 5.84,6.99 5.84,7.62 12.19,13.97 18.67,13.97 21.97,17.27 21.97,18.54 22.36,18.91 IC3.62
CN3_32
  Top 0.127: CN3.39 3.05,3.68 5.21,3.68 5.59,4.06 6.48,4.06 8.13,5.71 8.13,6.35 | 7.87,6.22 7.87,6.35 | 7.87,6.22 7.91,6.22 R14.1 | 8.13,6.35 R14.1 | 8.13,6.35 8.26,6.35 | R14.1 7.87,6.22 | R14.1 7.87,6.35 | 7.87,6.35 7.87,7.75 8.51,8.38 9.53,8.38 13.08,11.94 19.81,11.94 23.37,15.49 23.37,18.8 23.36,19.06 IC3.64
CN3_33
  Top 0.127: R12.2 9.4,4.19 10.54,5.21 10.54,9.02 13.21,11.68 19.94,11.68 23.62,15.37 23.62,18.54 23.88,18.8 23.86,19.07 IC3.65
CN3_33P
  Top 0.127: CN3.40 5.71,3.81 7.75,3.81 8.26,3.77 R12.1
  Bottom 0.127: R13.1 5.93,2.2
  Bottom 1.778: 5.93,2.2 5.08,2.16 CN3.40
CN3_CLK  (via drill 0.3)
  Top 0.127: v13.72,26.67 13.84,26.8 14.35,26.8 14.49,26.8 IC3.39
  Bottom 0.127: QG1.3 12.82,23.5 12.83,24 12.83,24.38 13.72,24.51 v13.72,26.67
CN3_GND  (via drill 0.3)
  Top 0.127: DIGITAL.2 47.06,44.89 47.12,44.83 | 47.12,47.88 47.12,44.83 | 47.12,47.88 45.85,47.88 DIGITAL.23 45.84,48.89 46.1,49.15 46.1,52.45 39.24,52.45 | DIGITAL.5 46.91,43.39 47.12,43.31 | 47.12,44.83 47.12,43.31 | 46.97,41.89 DIGITAL.8 | 46.97,41.89 47.12,41.91 47.12,43.31 | DIGITAL.11 46.99,40.39 47.12,40.39 | 46.97,41.89 47.12,41.87 47.12,41.78 | DIGITAL.17 46.94,37.39 47.12,37.47 | 47.12,40.39 47.12,37.47 | 47.12,37.47 47.12,33.66 46.85,33.39 DIGITAL.22 44.45,32 44.45,31.24 | 47.12,40.39 v46.48,40.39 | v38.23,18.41 38.1,18.41 38.1,16.38 | 38.1,16.38 42.29,16.38 | 42.29,16.38 42.97,16.38 HOST.P$1 | HOST.4 40.35,26.72 HOST.P$2 | 42.29,16.38 42.55,16.13 J1.2 42.83,11.79 45.72,8.89 45.72,7.16 J1.1 | v21.59,31.5 20.36,32.73 IC3.18 20.36,35.65 20.32,35.69 20.32,35.81 19.56,36.58 19.18,36.58 18.29,37.47 5.46,37.47 4.95,36.96 0.76,36.96 | v27.43,31.11 28.19,30.35 29.46,30.35 29.92,30.8 IC3.95 31.31,30.8 31.5,30.86 32.38,30.86 38.1,36.58 38.1,39.88 42.29,44.07 43.18,44.07 | v27.56,28.57 28.19,27.94 28.96,27.94 29.82,28.8 IC3.91 31.22,28.8 32,29.59 33.15,29.59 38.86,35.31 38.86,39.24 42.16,42.55 43.18,42.55 | v27.56,26.16 27.69,26.29 27.69,26.67 28.19,27.18 29.21,27.18 29.58,26.8 IC3.87 31.36,26.8 31.37,26.8 31.5,26.92 32.64,26.92 39.62,33.91 39.62,38.48 42.16,41.02 43.18,41.02 | IC3.74 28.36,20.41 28.07,20.7 28.07,21.34 27.69,21.72 27.69,23.24 v27.43,23.5 27.94,24 29.21,24 29.91,23.3 IC3.80 31.3,23.3 31.37,23.24 33.53,23.24 36.7,26.54 36.7,28.96 | IC3.68 25.36,20.15 25.59,20.38 | 25.59,20.38 25.78,20.57 25.78,21.84 v26.04,22.1 | 25.59,20.38 25.86,20.11 IC3.69 25.91,19.51 25.91,18.92 25.78,18.8 25.4,18.8
  Top 0.127: v21.59,22.61 22.86,21.34 IC3.63 22.86,16.76 21.84,15.75 21.84,14.73 19.56,12.45 12.19,12.45 6.99,7.24 6.99,5.97 4.95,3.94 2.41,3.94 2.16,3.68 0.76,3.68 | 18.16,22.73 16,22.73 15.93,22.8 IC3.47 14.48,22.8 14.35,22.73 12.7,21.08 11.56,21.08 10.92,21.72 10.03,21.72 7.87,19.56 6.22,19.56 5.59,18.92 3.81,18.92 3.17,18.29 3.17,15.24 | 18.16,22.73 v19.05,23.62 20.36,22.31 IC3.58 20.36,18.88 20.45,18.8 20.45,17.91 18.16,15.49 11.43,15.49 4.83,9.02 2.79,9.02 2.67,8.89 0.76,8.89 | v18.8,26.04 18.54,26.04 17.81,25.3 IC3.42 14.48,25.27 14.35,25.4 v9.91,25.4 9.65,25.4 5.84,21.46 3.81,21.46 3.17,20.83 3.17,19.81 2.29,18.92 0.76,18.92 | 25.86,34.08 IC3.7 | 25.86,34.08 26.04,33.91 v26.04,32.64 26.04,32.51 25.4,31.88 24.26,31.88 v24.13,32 22.61,33.53 22.61,33.78 22.36,34.03 IC3.14 22.36,35.69 22.35,36.2 22.23,36.32 21.97,36.32 19.18,39.12 7.11,39.11 5.59,40.64 5.59,40.63 CN3.10 | 30.86,37.34 30.86,36.45 31.37,35.94 31.37,33.78 29.72,33.78 29.08,33.15 26.04,33.15 | 25.86,34.08 25.81,34.04 25.4,34.04 25.36,34.08 IC3.8 25.4,35.6 25.4,35.69 25.65,35.94 | 17.86,34.04 17.86,33.07 v19.05,31.88 | 17.86,34.04 IC3.23 17.78,35.31 | IC3.24 17.36,34.12 17.4,34.04 | 17.78,34.04 17.86,34.04 | 17.4,34.04 17.78,34.04 | 17.78,35.43 17.78,36.07 17.4,36.07 | 0.76,40.64 CN3.9 CN3.10 | 3.17,45.09 2.54,44.45 0.76,44.45 | 0.76,40.64 0.76,44.45 | 0.76,44.45 0.76,47.12 | 0.76,47.12 5.71,47.12 9.53,43.31 17.91,43.31 v22.73,38.48 23.11,38.48 25.65,35.94 | 25.65,35.94 25.91,35.69 25.91,35.56 25.78,35.56 25.78,35.43 | C4.2 12.57,50.8 10.03,50.76 C5.2 10.07,50.97 9.14,50.42 v9.14,51.69 9.14,52.45
  Top 0.127: 9.14,52.45 21.59,52.45 | 31.75,52.45 39.24,52.45 | 31.75,52.45 JTAG.10 30.73,48.51 | 21.59,52.45 31.75,52.45 | 21.59,52.45 JTAG.2 | 9.14,52.45 0.76,52.45 0.76,49.53 | 3.17,50.16 2.54,49.53 0.76,49.53 | 0.76,47.12 0.76,49.53 | JP1.1 39.37,52.32 39.24,52.45 | 47.12,47.88 47.12,48.77 47.37,49.02 50.21,49.02 DIGITAL.21 | 47.12,41.78 47.12,40.39 | 47.12,41.78 51.82,41.78 51.82,33.4 50.64,32.89 DIGITAL.20 | v41.02,38.1 40.64,37.72 40.64,32.89 36.7,28.96 | HOST.P$2 42.16,29.46 41.66,28.96 36.7,28.96 | 44.45,31.24 44.45,30.86 43.18,29.59 43.18,29.55 HOST.P$2 | 0.76,18.92 0.76,21.59 | 3.17,24.77 2.54,24.13 0.76,24.13 | 0.76,21.59 0.76,24.13 | 0.76,24.13 0.76,29.08 | 7.75,28.45 5.71,28.45 5.08,29.08 0.76,29.08 | 0.89,31.88 0.76,31.88 | 0.89,31.88 9.65,31.88 | 0.76,29.08 0.76,32 | 0.76,34.42 0.76,36.96 | 0.76,36.96 0.76,40.64 | v36.7,3.05 36.7,3.81 34.29,3.81 | 33.66,3.81 C1.2 34.29,3.81 | 34.29,5.08 34.29,3.81 | 34.29,9.91 34.16,9.78 34.16,8.26 C3.2 34.29,7.83 34.29,5.08 | 34.29,9.91 32.64,9.91 LED1.K 29.84,10.79 29.21,10.16 C2.2 | v18.41,8.26 18.41,6.48 18.2,6.26 C10.2 18.54,6.01 18.54,3.81 | v11.43,8.26 11.43,6.35 12.83,6.35 | 18.54,3.81 SERIAL.4 26.92,3.81 28.19,5.08 34.29,5.08 | 12.83,6.35 C7.2 | 12.83,3.81 12.83,6.35 | 12.83,3.81 18.54,3.81 | R7.2 30.86,36.83 30.86,39.5 IC9.1 30.73,39.62 30.73,48.51 | 3.17,15.24 CN3.30 | 0.76,15.24 CN3.29 3.17,15.24 | 0.76,6.35 0.76,0.89 0.89,0.76 12.19,0.89 13.08,0.89 12.83,1.14 12.83,3.81 | 3.17,6.99 2.54,6.35 0.76,6.35 | 0.76,6.35 0.76,8.89 | 0.76,8.89 0.76,11.3 | 18.16,22.73 14.86,19.43 v14.86,17.53 9.65,17.53 5.97,13.84 3.81,13.84 3.17,13.21 3.17,12.19 | 3.17,12.19 2.29,11.3 0.76,11.3
  Top 0.127: 3.17,12.19 3.81,11.56 5.59,11.56 7.37,13.34 | 0.76,11.3 0.76,15.24 | 0.76,15.24 0.76,18.92 | 30.73,48.51 22.99,48.51 22.99,42.16 v23.5,42.16 24.64,42.16 24.64,42.04 | 34.29,9.91 38.1,13.72 38.1,16.38 | 49.53,22.1 45.21,22.1 43.81,20.7 40.01,20.7 39.24,21.46 39.24,24.38 39.88,25.02 43.43,25.02 45.21,23.24 49.53,23.24 | 49.53,22.1 v49.53,27.43 49.53,28.7 46.99,31.24 44.45,31.24 | 49.53,22.1 v49.53,18.54 | 17.4,36.07 6.99,36.07 5.33,34.42 0.76,34.42 | 17.4,36.07 17.4,34.04 | 17.78,35.43 17.86,35.35 | 0.76,21.59 2.54,21.59 3.05,22.1 3.05,23.37 3.68,24 5.97,24 8.89,26.92 v9.91,26.92 | 17.78,34.04 17.78,35.31 | 17.78,35.43 17.78,35.31 | 25.4,18.8 25.4,19.43 | 25.4,18.8 25.4,14.99 23.5,13.08 23.5,3.81 | 0.76,32 0.76,34.42 | 0.76,32 0.89,31.88
  Bottom 0.127: 45.45,41.51 45.34,41.63 | 45.34,41.63 IC10.7 | IC10.10 43.83,35.45 43.81,34.54 43.81,34.16 43.05,33.4 42.42,33.4 41.91,33.91 41.91,35.3 | 41.91,35.3 IC10.13 | 37.59,17.14 R15.1 38.23,17.53 v38.23,18.41 | 46.66,21.26 DEV.5 | 46.66,21.26 46.99,21.46 | 46.99,21.72 46.7,21.97 DEV.4 | 45.86,18.43 DEV.M4 | 45.86,18.43 46.61,19.18 | 46.61,20.83 46.61,21.18 46.66,21.26 | 46.61,26.42 46.74,26.54 46.74,27.18 46.6,27.31 DEV.M3 45.18,27.31 | 45.2,18.43 45.86,18.43 | 18.92,29.84 C24.2 | 18.92,27.6 C14.2 18.92,27.3 | 18.92,25.06 C16.2 19.05,24.77 | 20.32,23.24 C23.2 20.32,23.11 20.45,23.24 | 22.69,23.24 C12.2 | 18.07,31.24 C17.2 | 20.19,31.24 20.32,31.37 C11.2 | 22.69,31.37 C18.2 23.03,31.24 | v21.59,31.5 21.59,31.37 | C19.2 27.43,32.04 | 27.43,28.57 v27.56,28.57 27.43,28.45 | 27.43,29.5 C21.2 | 27.43,26.16 v27.56,26.16 | 27.43,26.96 C22.2 | 27.43,24.42 C13.2 | C20.2 27.05,22.1 26.92,22.23 | 21.46,23.24 21.59,23.11 | v19.05,23.62 19.05,23.24 | 17.69,23.24 17.82,23.24 C15.2 17.69,23.24 | 17.69,23.24 17.53,23.11 | 18.92,26.04 v18.8,26.04 | 19.05,31.37 18.92,31.24 | 23.37,38.48 23.5,38.12 23.24,38.12 | v9.14,51.69 9.13,51.45 | R27.1 50.38,35.27 50.42,34.92 | 39.41,38.95 C9.2 | 39.41,38.95 39.59,38.95 39.37,38.99 39.5,38.73 39.41,38.95 | v41.02,38.1 41.15,37.85 41.15,36.83 41.91,36.07 41.91,35.3 | QG1.2 8.89,23.74 9.21,24.07 9.34,24.07 9.91,24.89 9.53,23.88 | 14.86,16.76 C8.2 | IC1.1 35.32,2.4 35.69,3.05 | IC6.7 11.56,6.86 | 10.79,5.08 IC8.4 | 17.78,5.21 IC7.4 | 18.41,6.13 C10.2 18.2,6.64 IC5.7 | 51.31,18.41 DEV.M1 51.39,18.49 | IC4.1 27.3,37.85 27.3,38.48 27.05,38.73 25.65,38.73 25.4,38.48 IC4.4 25.4,37.08 25.15,36.83 23.62,36.83 23.37,37.08 23.37,37.72
  Bottom 0.127: 24.77,43.43 24.64,43.56 | 24.64,43.56 IC4.10 24.77,43.43 | IC4.13 26.67,43.56 26.67,44.58 26.04,45.21 25.27,45.21 24.64,44.58 24.64,43.56 | 41.02,41.66 IC10.1 | 41.15,41.91 41.27,40.64 | 43.18,41.91 IC10.4 | 45.34,41.63 45.34,41.78 | 24.77,43.43 24.77,42.8 24.13,42.16 v23.5,42.16 | 23.37,38.48 23.37,37.72 | 23.37,38.48 IC4.7 23.37,37.72 | J1.2 42.55,11.81 | 51.31,27.36 DEV.M2 | 23.24,38.48 23.37,38.48
  Bottom 0.61: v46.48,40.39 46.1,40.77 45.47,40.77 45.45,41.51 | 18.92,27.6 18.92,29.84 18.92,31.24 | 18.92,25.06 18.92,26.04 18.92,27.3 | v19.05,23.62 19.05,24.77 | 20.32,23.24 19.05,23.24 17.82,23.24 | 20.45,23.24 21.46,23.24 22.69,23.24 | 18.92,31.24 18.07,31.24 | 18.92,31.24 20.19,31.24 | 20.45,31.24 21.59,31.24 | 20.45,31.24 20.45,31.37 | 20.32,31.37 20.45,31.24 | 21.59,31.37 21.59,31.24 | 21.59,31.24 22.73,31.24 22.69,31.37 | v24.13,32 24.13,31.24 23.03,31.24 | 27.43,32.04 v27.43,31.11 27.43,29.5 27.43,28.57 | 26.92,22.23 26.92,23.5 v27.43,23.5 27.43,24.42 27.43,26.16 27.43,26.96 27.43,28.45 | C20.2 v26.04,22.1 | 21.59,23.11 v21.59,22.61 | v26.04,32.64 26.29,32.38 C19.2 | v19.05,31.88 19.05,31.37 | v41.02,38.1 41.02,38.73 | v18.41,8.26 IC5.7 | v11.43,8.26 IC6.7 11.43,5.71 10.79,5.08 | 17.78,5.21 18.41,5.84 18.41,6.13 | 41.02,38.73 41.02,41.66 | 41.02,38.73 39.5,38.73 | 45.34,41.78 44.96,42.16 43.05,42.16 | 43.05,42.16 43.18,41.91 | 43.05,42.16 41.4,42.16 41.15,41.91 | 22.86,38.48 23.24,38.12 | 22.86,38.48 23.24,38.48 | v22.73,38.48 22.86,38.48
  Bottom 1.016: R16.1 39.41,27.3 HOST.4 | 46.99,21.46 46.99,21.72 | 46.61,19.18 46.61,20.83 | HOST.P$2 45.18,27.31 | HOST.P$1 45.2,18.43 | 50.42,34.92 50.42,33.11 DIGITAL.20 | 9.91,24.89 v9.91,25.4 v9.91,26.92 | v14.86,17.53 14.86,16.76 | v36.7,3.05 35.69,3.05 | v49.53,18.54 51.31,18.54 51.39,18.49 | v49.53,27.43 51.31,27.43 51.31,27.36
  Bottom 1.27: 9.13,51.45 IC2.1
  pour Top (isolate 0.254): 52.7,52.7 52.7,0.64 0.64,0.64 0.64,52.7
CN3_IN  (via drill 0.3)
  Top 0.127: v31.75,31.62 31.75,31.75 30.73,31.75 IC3.97 | v33.15,34.67 36.07,37.59 36.07,44.96 JP1.2
  Bottom 0.127: R24.2 36.7,48.26 JP1.2 | v31.75,31.62 31.75,33.27 v33.15,34.67
CN3_POW5
  Bottom 0.127: 6.99,27.94 R11.1 6.86,28.07 6.1,28.45
  Bottom 1.778: CN3.20 5.08,28.45 6.1,28.45
CN3_RXD  (via drill 0.3)
  Top 0.127: v34.42,25.15 34.42,24.64 33.66,23.88 33.27,23.88 32.89,24.26 30.73,24.26 IC3.82
  Bottom 0.127: v34.42,25.15 34.42,25.91 34.04,26.29 33.27,26.29 32.13,25.15 32.13,21.97 32.64,21.46 32.64,18.8 30.61,16.76 29.21,16.76 26.54,14.1 26.54,10.03 SERIAL.2
CN3_TXD  (via drill 0.3)
  Top 0.127: v32.38,28.83 31.88,28.32 30.73,28.32 IC3.90
  Bottom 0.127: v32.38,28.83 31.88,28.32 31.88,21.84 32.38,21.34 32.38,18.92 30.48,17.02 29.08,17.02 26.29,14.22 26.29,12.32 SERIAL.1
CONF_CCLK  (via drill 0.3)
  Top 0.127: v71.5,64.77 72.61,64.77 IC201.3
  Bottom 0.127: CONF.P$7 61.09,62.48 62.23,63.63 63.37,63.63 65.53,65.79 69.34,65.79 69.85,65.28 70.99,65.28 v71.5,64.77
CONF_CSO_B  (via drill 0.3)
  Top 0.127: IC201.8 66.8,67.31 v65.53,67.31
  Bottom 0.127: v65.53,67.31 64.52,67.31 63.37,66.17 62.36,66.17 60.83,64.64 58.29,64.64 CONF.P$9
CONF_D0  (via drill 0.3)
  Top 0.127: v68.2,64.52 68.2,64.64 67.06,64.64 IC201.12
  Bottom 0.127: 68.83,63.37 68.96,63.5 R202.1 | 68.83,63.37 62.36,63.37 60.45,61.47 57.78,61.47 56.9,62.36 56.39,62.36 56.26,62.48 CONF.P$8 | 68.83,63.37 68.96,63.37 | 68.83,63.37 68.83,63.88 v68.2,64.52
CONF_GND  (via drill 0.3)
  Top 0.127: 64.39,58.42 67.06,58.42 | 67.06,58.42 67.44,58.42 | 67.06,58.42 IC202.10 | 64.39,58.29 64.39,56.52 66.93,56.52 IC202.13 67.06,56.52 69.85,56.52 69.85,58.42 71.12,59.69 72.64,59.69 | PIC.3 64.39,63.25 64.39,61.34 | 54.74,60.58 56.13,60.58 CONF.P$6 | 54.74,60.58 54.74,70.48 56.13,70.48 CONF.P$16 56.26,70.61 54.74,70.61 54.74,77.47 PROG.3 57.15,78.74 68.58,78.74 LED201.K | IC202.4 72.39,57.78 72.26,57.91 72.14,57.78 IC202.4 | 75.95,57.78 75.95,55.88 72.64,55.88 IC202.1 | 75.95,57.78 IC202.4 | 75.95,59.69 75.95,58.67 | 75.95,58.67 75.95,57.78 | 72.64,59.69 IC202.7 | IC202.7 72.77,59.69 | 72.64,59.69 72.77,59.69 | 72.77,59.69 75.95,59.69 | 75.95,59.69 75.95,59.94 78.36,62.36 78.36,64.26 79.38,65.28 80.77,65.28 81.28,65.79 81.28,68.58 81.15,68.71 81.15,69.6 80.39,70.48 73.91,70.48 72.39,68.96 v72.39,68.07 72.39,67.33 IC201.7 72.77,67.44 70.1,67.44 69.47,66.8 69.47,63.37 67.31,61.21 64.52,61.21 64.39,61.34 | 75.95,58.67 82.55,58.67 FPGA.10 82.55,60.07 94.61,60.07 SPI.10 97.16,61.59 97.16,71.75 SPI.2 94.61,74.3 82.55,74.3 | LED201.K 70.99,77.34 80.64,77.34 82.55,75.44 82.55,74.3 | 82.55,74.3 FPGA.2 | PIC.6 66.04,72.39 LED201.K | 54.74,60.58 54.74,59.56 59.56,59.56 60.83,58.29 64.39,58.29 | 64.39,58.29 64.39,61.34 | v72.52,60.71 72.52,59.97 IC202.7
  Bottom 0.127: 70.61,68.58 C202.2 71.88,68.58 v72.39,68.07 | C201.2 70.74,60.96 70.99,60.71 v72.52,60.71
  pour Top (isolate 0.254): 53.98,79.38 53.98,53.98 99.06,53.98 99.06,79.38
CONF_MOSI  (via drill 0.3)
  Top 0.127: IC201.6 72.64,66.67 v71.37,66.67
  Bottom 0.127: v71.37,66.67 64.26,66.67 63.5,65.91 62.48,65.91 60.2,63.63 57.02,63.63 CONF.P$10
CONF_PROG_B  (via drill 0.3)
  Top 0.127: 65.79,66.04 66.93,66.04 IC201.10 | IC201.13 66.93,64.14 66.17,64.14 65.79,64.52 65.79,66.04 | 65.79,66.04 v64.77,66.04 61.09,66.04 59.05,68.07 59.05,69.47 | 70.87,65.41 70.87,64.01 71.37,63.5 72.9,63.5 72.64,63.37 IC201.1 | v70.36,65.91 70.87,65.41 | 70.87,65.41 IC201.4 | 59.05,69.47 57.78,69.47 57.28,68.96 57.28,61.47 58.17,60.58 58.04,60.45 CONF.P$5 | 59.05,69.47 59.69,70.1 PROG.2
  Bottom 0.127: PROG.2 59.69,73.66 R210.1 | v70.36,65.91 70.23,66.04 v64.77,66.04
CONF_VCC  (via drill 0.3)
  Top 0.127: 66.93,55.88 IC202.14 66.91,55.75 v65.79,55.75 | v67.06,62.48 67.06,63.37 IC201.14
  Bottom 0.127: 57.28,73.53 55.24,71.5 55.24,67.44 | 57.28,73.53 57.78,73.53 R210.2 | 55.24,67.44 56.9,67.44 57.91,66.42 CONF.P$11 58.23,66.42 | 76.2,71.63 76.07,71.75 R205.2 | FPGA.4 81.28,70.48 75.82,70.48 | R203.2 88.14,66.67 | R201.2 88.14,71.75 88.01,71.88 88.27,71.88 88.27,73.41 | 76.07,62.74 75.31,63.5 70.74,63.5 | 76.07,62.74 76.07,61.59 R208.2 | R207.2 76.07,66.67 76.07,65.66 88.05,65.66 R203.2 | 76.07,62.74 87.5,62.61 88.39,61.72 88.27,61.59 | 88.27,61.59 R204.2 | C202.1 68.96,68.58 68.96,71.12 R209.2 | 69.09,60.45 69.09,62.23 70.74,62.23 70.74,63.5 | 69.09,60.45 70.74,58.8 70.74,57.15 R206.2 | 69.09,60.45 C201.1 67.44,62.48 v67.06,62.48 | C202.1 68.83,68.83 66.04,68.83 63.75,71.12 59.56,71.12 58.42,72.26 58.42,72.39 57.28,73.53 | 70.61,63.75 70.61,63.5 R202.2 70.74,63.5 | C202.1 69.09,68.58 68.83,67.44 72.77,67.44 75.82,70.48 | R205.2 76.2,71.63 | v65.79,55.75 65.79,54.61 54.36,54.61 54.36,67.44 55.24,67.44 | 93.34,69.22 93.34,65.15 88.39,65.15 88.39,66.8 88.01,66.71 R203.2 | 88.27,73.41 93.34,73.41 93.34,69.22 | 93.34,69.22 SPI.4 96.39,69.22 96.39,59.56 96.27,59.44 88.27,59.44 88.27,61.59 | 76.2,71.63 76.2,73.41 88.27,73.41 | 75.82,70.48 75.82,71.59 R205.2
  pour Bottom (isolate 0.254): 53.98,79.63 53.98,53.98 99.06,53.98 99.06,79.63
CONF_VDD
  Top 0.127: PIC.2 61.72,63.37 61.72,64.9 58.17,68.45 CONF.P$13
CONF_XTCK
  Top 0.127: IC202.3 72.9,57.15 71.88,57.15 69.6,54.86 61.47,54.86 59.94,56.39 58.17,56.39 CONF.P$1
CONF_XTDI
  Top 0.127: IC202.6 72.77,59.18 72.14,59.18 71.37,58.42 71.37,57.02 69.47,55.12 61.59,55.12 59.18,57.53 57.15,57.53 56.26,58.42 CONF.P$4
CONF_XTDO  (via drill 0.3)
  Top 0.127: v65.79,57.15 66.93,57.15 IC202.12
  Bottom 0.127: 65.79,57.4 57.15,57.4 56.26,56.52 CONF.P$2 | 65.79,57.4 68.71,57.4 68.96,57.15 R206.1 | 65.79,57.4 v65.79,57.15
CONF_XTMS  (via drill 0.3)
  Top 0.127: v65.91,59.69 66.93,59.69 IC202.8
  Bottom 0.127: v65.91,59.69 63.88,57.66 59.18,57.66 58.29,58.55 58.17,58.55 CONF.P$3
CSO_B  (via drill 0.3)
  Top 0.127: v13.97,33.66 13.97,33.15 14.35,32.77 IC3.27 | v15.49,13.34 15.88,13.72 18.8,13.72 20.19,15.11 v20.95,15.11
  Bottom 0.127: IC7.1 21.59,9.27 20.95,9.91 IC5.4 v20.95,15.11 | v15.49,13.34 15.49,14.48 14.73,15.24 12.19,15.24 11.68,15.75 11.68,19.81 12.06,20.19 12.06,20.95 11.56,21.46 11.43,21.46 11.05,21.84 11.05,22.35 12.06,23.37 12.06,26.29 13.72,27.94 13.72,28.7 14.61,29.59 14.61,32.38 13.97,33.02 v13.97,33.66
D0  (via drill 0.3)
  Top 0.127: v16.51,18.41 16.76,18.67 16.76,19.05 IC3.51
  Bottom 0.127: IC5.8 17.14,7.87 18.41,9.14 | 18.41,9.14 18.67,8.89 20.07,8.89 20.32,8.64 IC7.2 | 18.41,9.14 18.41,11.94 18.16,12.19 17.91,12.19 17.78,12.32 17.78,14.61 17.53,14.86 17.53,17.4 v16.51,18.41
DE0_1  (via drill 0.3)
  Top 0.127: DE0.2 DE0.1 SP3.1 2.54,65.53 1.4,66.67 1.4,68.07 4.06,70.74 9.53,70.74 11.56,72.77 v11.56,73.41 11.56,74.59 REV.3
  Bottom 0.127: REV.3 11.57,74.03 v11.56,73.41
DE0_3  (via drill 0.3)
  Top 0.127: DE0.4 DE0.3 3.68,61.09 3.68,66.17 SP3.2 2.54,67.82 5.21,70.48 11.05,70.48 v13.46,72.9 13.46,73.66 13.59,73.79 13.59,74.6 REV.7
  Bottom 0.127: 13.57,73.77 REV.7 | 13.57,73.77 13.59,73.79 | 13.57,73.77 13.46,73.66 v13.46,72.9
DE0_3V3  (via drill 0.3)
  Top 0.127: v28.57,73.41 REV.37 | REV.38 29.07,74.05 29.08,73.91 v28.57,73.41 | v29.97,73.41 29.59,73.79 REV.39 | REV.40 30.07,74.01 29.97,73.91 v29.97,73.41 | v29.97,73.41 v28.57,73.41 | v29.97,73.41 33.91,69.47 37.59,69.47 39.37,67.69 39.37,60.96 DE0.29
  Bottom 0.127: REV.37 28.57,73.92 28.57,73.91 v28.57,73.41 29.08,73.91 29.07,73.93 REV.38 | REV.39 29.59,73.79 v29.97,73.41 29.97,73.91 30.1,74.04 REV.40
  Bottom 0.61: SP3.19 27.81,62.36 35.43,62.36 DE0.29
  pour Top (isolate 0.254): 0.64,79.38 0.64,53.98 52.7,53.98 52.7,79.38
DE0_4  (via drill 0.3)
  Top 0.127: DE0.5 5.08,62.23 SP3.3 5.08,65.66 3.94,66.8 3.94,68.07 6.1,70.23 11.81,70.23 14.1,72.52 v14.1,73.41 14.1,74.61 REV.8
  Bottom 0.127: REV.8 14.07,74.01 14.1,74.04 v14.1,73.41
DE0_5  (via drill 0.3)
  Top 0.127: DE0.6 8.76,58.29 8.76,60.07 6.22,62.61 6.22,66.17 SP3.4 5.08,67.82 7.24,69.98 12.19,69.98 14.73,72.52 v14.73,72.9 14.73,73.79 14.61,73.91 14.61,74.61 REV.9
  Bottom 0.127: REV.9 14.57,74.01 14.73,73.79 v14.73,72.9
DE0_5V
  Bottom 0.406: 24.13,62.87 24.13,66.04
  Bottom 0.61: DE0.11 15.24,60.2 16.51,61.47 22.61,61.47 24.13,62.87 | 24.13,66.04 SP3.20
DE0_6  (via drill 0.3)
  Top 0.127: DE0.7 7.62,62.23 SP3.5 7.62,65.53 6.35,66.8 6.35,67.94 8.13,69.72 12.45,69.72 15.37,72.64 v15.37,73.41 15.37,73.53 15.62,73.79 15.62,74.63 REV.11
  Bottom 0.127: REV.11 15.57,73.71 15.37,73.53 v15.37,73.41
DE0_7  (via drill 0.3)
  Top 0.127: DE0.8 11.3,58.29 11.3,60.07 8.76,62.61 8.76,66.17 SP3.6 7.62,67.94 9.14,69.47 12.83,69.47 16,72.64 v16,72.9 16,73.91 16.07,73.98 REV.12
  Bottom 0.127: REV.12 16.07,73.98 16,73.91 v16,72.9
DE0_8  (via drill 0.3)
  Top 0.127: DE0.9 10.16,62.23 SP3.7 10.16,65.53 9.02,66.67 9.02,68.07 10.16,69.22 13.34,69.22 16.64,72.52 v16.64,73.41 16.64,73.91 16.57,73.98 REV.13
  Bottom 0.127: REV.13 16.57,73.97 16.64,73.91 v16.64,73.41
DE0_9  (via drill 0.3)
  Top 0.127: DE0.10 13.84,58.29 13.84,60.07 11.3,62.61 11.3,66.17 SP3.8 10.16,68.07 11.05,68.96 14.1,68.96 17.4,72.26 v17.4,72.9 17.4,73.66 17.57,73.83 REV.15
  Bottom 0.127: REV.15 17.57,73.87 17.53,73.79 17.4,73.66 v17.4,72.9
DE0_10  (via drill 0.3)
  Top 0.127: DE0.13 15.24,62.23 SP3.11 14.1,65.91 14.1,68.2 18.03,72.14 v18.03,73.41 18.03,73.91 18.07,73.95 REV.16
  Bottom 0.127: v18.03,73.41 18.03,74.54 REV.16
DE0_11  (via drill 0.3)
  Top 0.127: DE0.14 18.92,58.29 18.92,60.07 16.38,62.61 16.38,66.17 SP3.12 15.24,68.83 18.67,72.26 v18.67,72.9 18.67,73.79 18.57,73.89 REV.17
  Bottom 0.127: v18.67,72.9 18.67,73.79 18.54,73.91 18.54,74.55 REV.17
DE0_12  (via drill 0.3)
  Top 0.127: DE0.15 17.78,62.23 SP3.13 17.78,65.79 16.51,67.06 16.51,69.34 19.43,72.26 v19.43,73.41 19.57,73.55 REV.19
  Bottom 0.127: v19.43,73.41 19.56,73.53 19.56,74.57 REV.19
DE0_13  (via drill 0.3)
  Top 0.127: DE0.16 21.46,58.29 21.46,60.07 18.92,62.61 18.92,66.17 SP3.14 17.78,69.98 20.07,72.26 v20.07,72.9 20.07,73.66 REV.20
  Bottom 0.127: v20.07,72.9 REV.20
DE0_14  (via drill 0.3)
  Top 0.127: DE0.17 20.32,62.23 SP3.15 20.32,65.79 18.92,67.18 18.92,70.48 20.7,72.26 v20.7,73.41 20.57,73.54 REV.21
  Bottom 0.127: v20.7,73.41 20.57,73.53 REV.21
DE0_15  (via drill 0.3)
  Top 0.127: DE0.18 24,58.29 24,60.07 21.46,62.61 21.46,66.17 SP3.16 20.32,71.12 21.46,72.26 v21.46,72.9 21.46,73.79 21.59,73.91 21.57,73.93 LCD.18
  Bottom 0.127: v21.46,72.9 21.46,73.79 21.59,73.91 21.59,74.56 LCD.18
DE0_16  (via drill 0.3)
  Top 0.127: DE0.19 22.86,62.23 SP3.17 22.86,65.79 21.59,67.06 21.59,71.63 22.1,72.14 v22.1,73.41 22.1,73.66 22.07,73.69 LCD.17
  Bottom 0.127: v22.1,73.41 22.1,74.55 LCD.17
DE0_17  (via drill 0.3)
  Top 0.127: DE0.20 26.54,58.29 26.54,60.07 24,62.61 24,66.17 SP3.18 22.61,67.56 22.61,72.77 v22.73,72.9 22.73,73.79 22.57,73.95 LCD.16
  Bottom 0.127: v22.73,72.9 22.73,73.79 22.61,73.91 22.61,74.54 LCD.16
DE0_18  (via drill 0.3)
  Top 0.127: DE0.21 SP3.21 26.8,65.91 26.8,68.83 23.5,72.14 v23.5,73.41 23.62,73.66 23.57,73.71 LCD.14
  Bottom 0.127: v23.5,73.41 23.62,73.66 23.62,74.53 LCD.14
DE0_19  (via drill 0.3)
  Top 0.127: DE0.22 29.08,58.29 29.08,66.17 SP3.22 27.94,68.33 24.13,72.14 v24.13,72.77 24.13,73.66 24.07,73.72 LCD.13
  Bottom 0.127: v24.13,72.77 24.13,73.66 24.07,73.72 LCD.13
DE0_20  (via drill 0.3)
  Top 0.127: DE0.23 SP3.23 30.48,65.79 29.21,67.06 29.21,67.69 24.77,72.14 v24.77,73.41 24.77,73.53 24.57,73.72 LCD.12
  Bottom 0.127: SP3.23 30.48,64.9 | LCD.12 24.57,73.79 24.77,73.59 v24.77,73.41
DE0_21  (via drill 0.3)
